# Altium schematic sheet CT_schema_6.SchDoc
size 586 x 434 mm
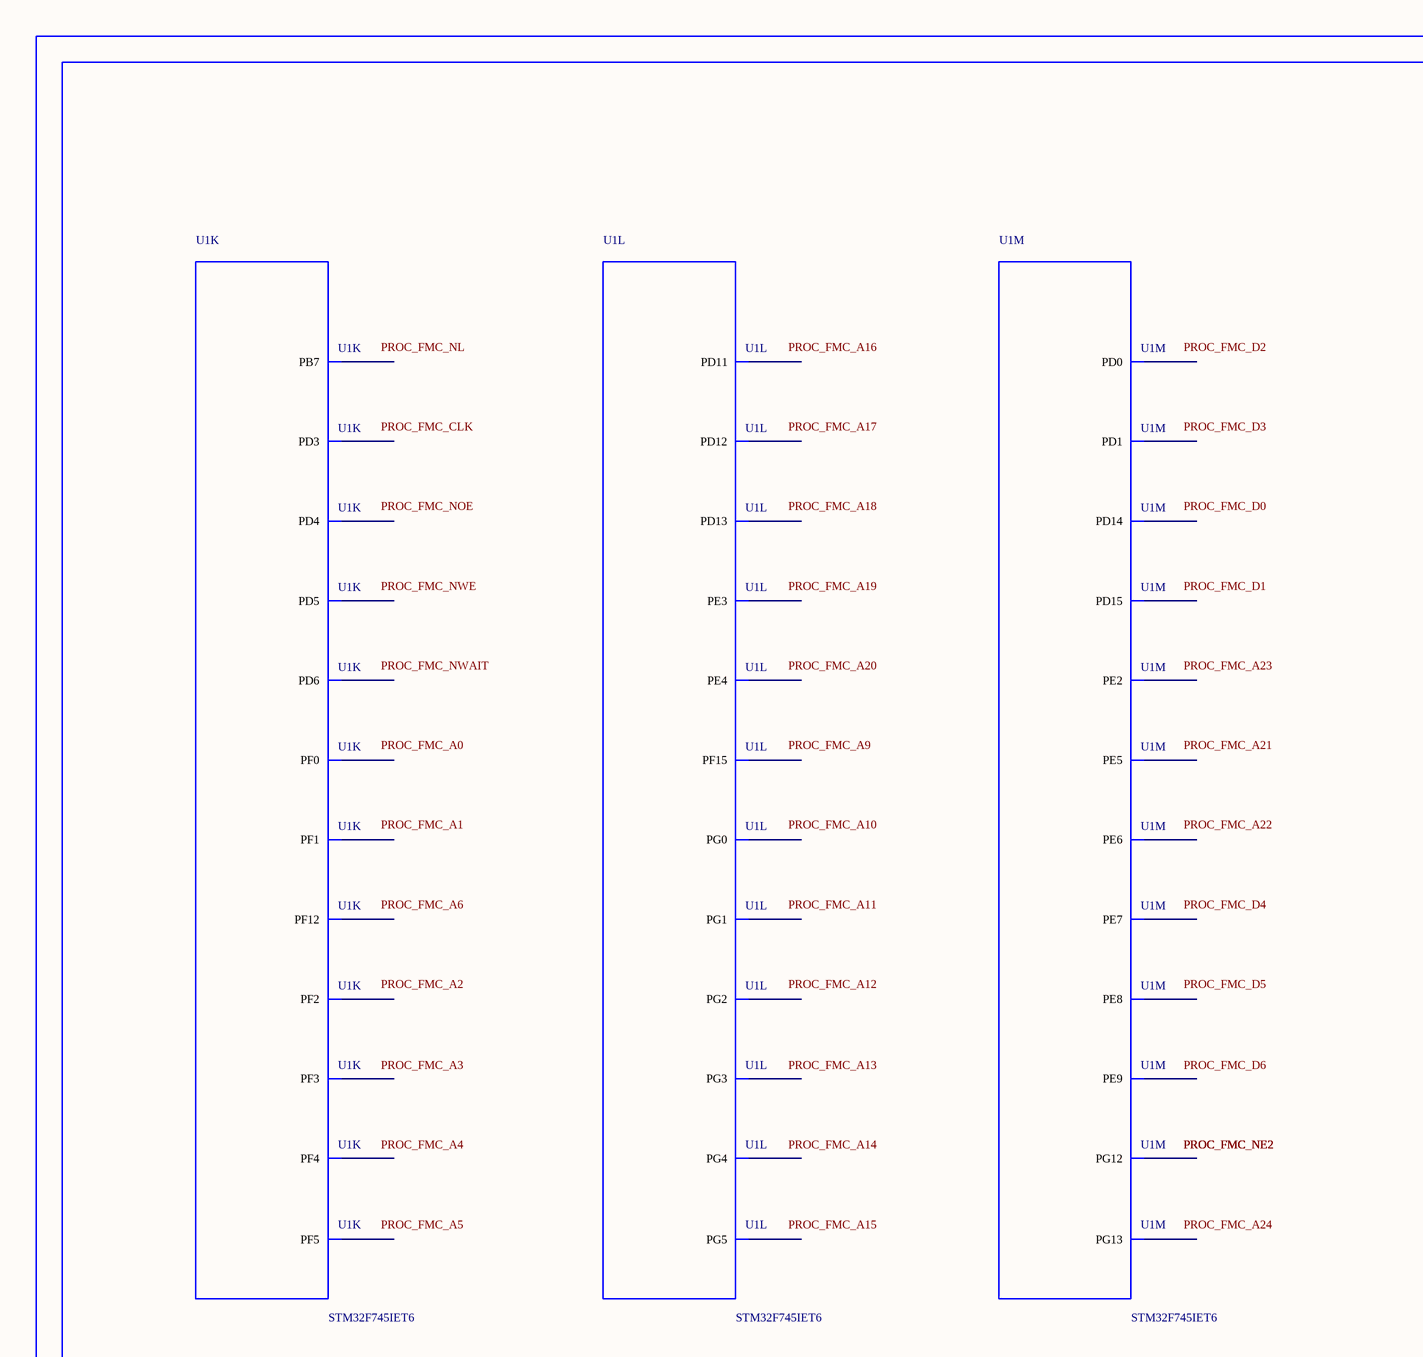
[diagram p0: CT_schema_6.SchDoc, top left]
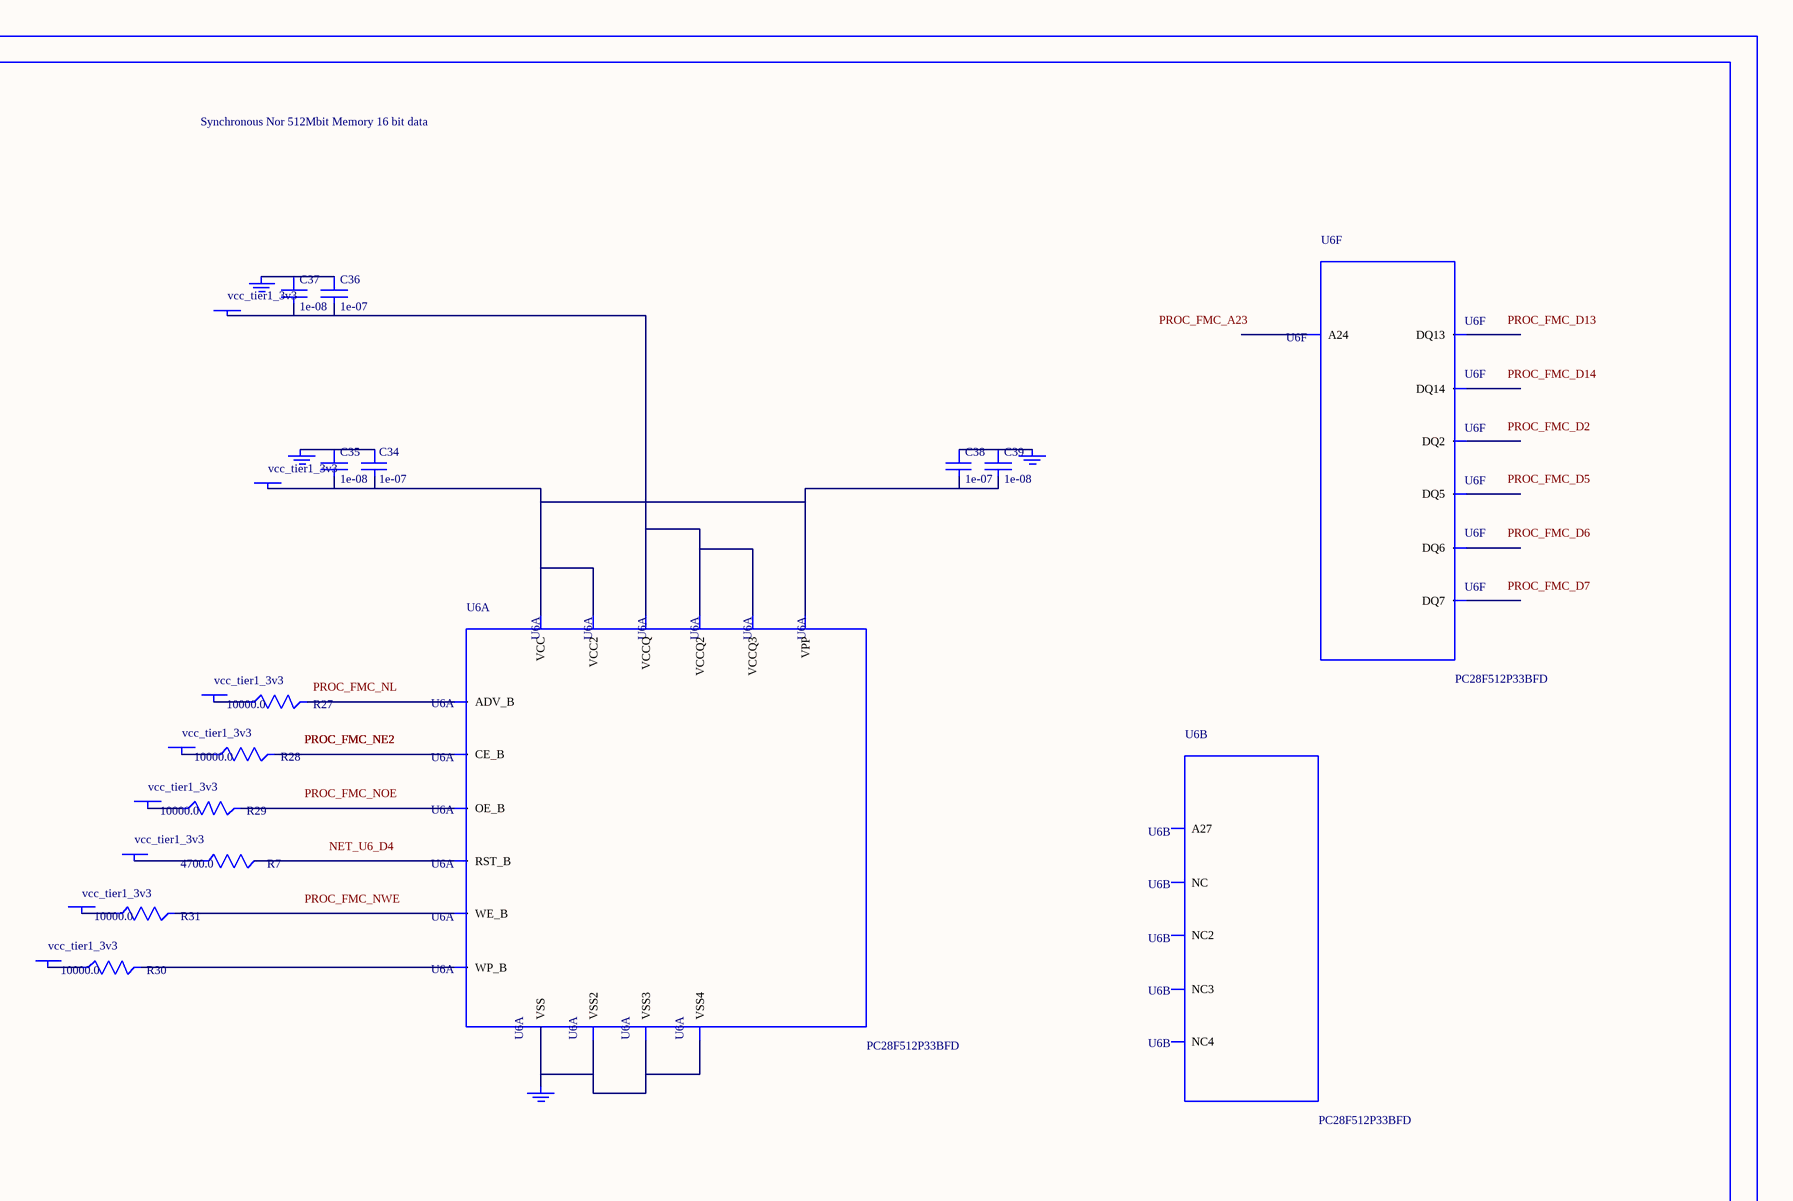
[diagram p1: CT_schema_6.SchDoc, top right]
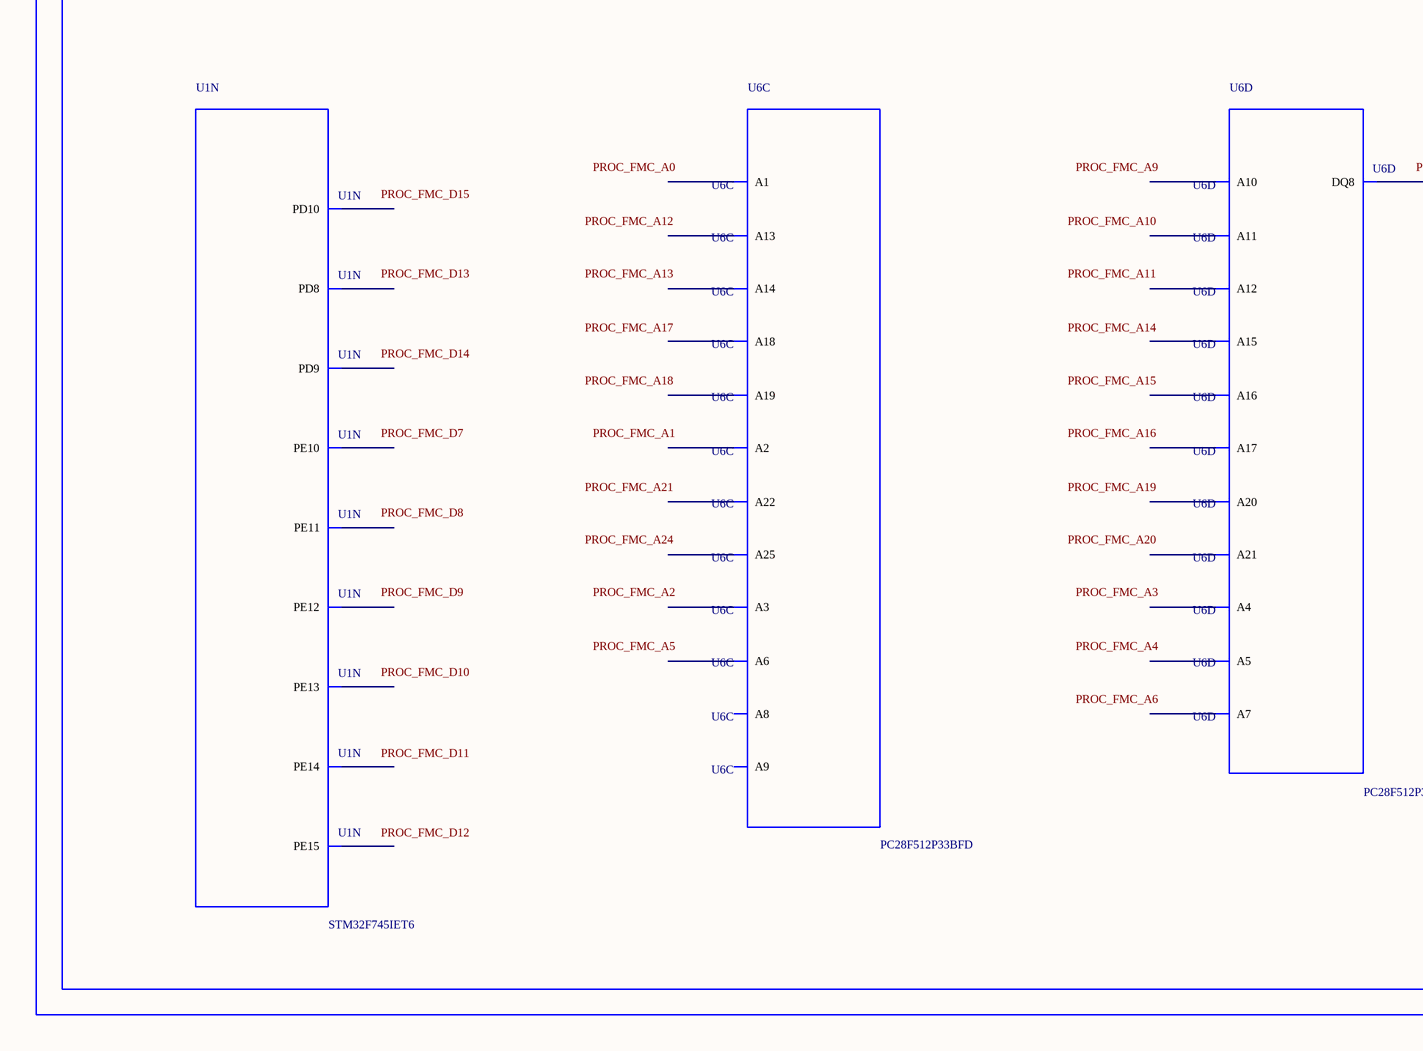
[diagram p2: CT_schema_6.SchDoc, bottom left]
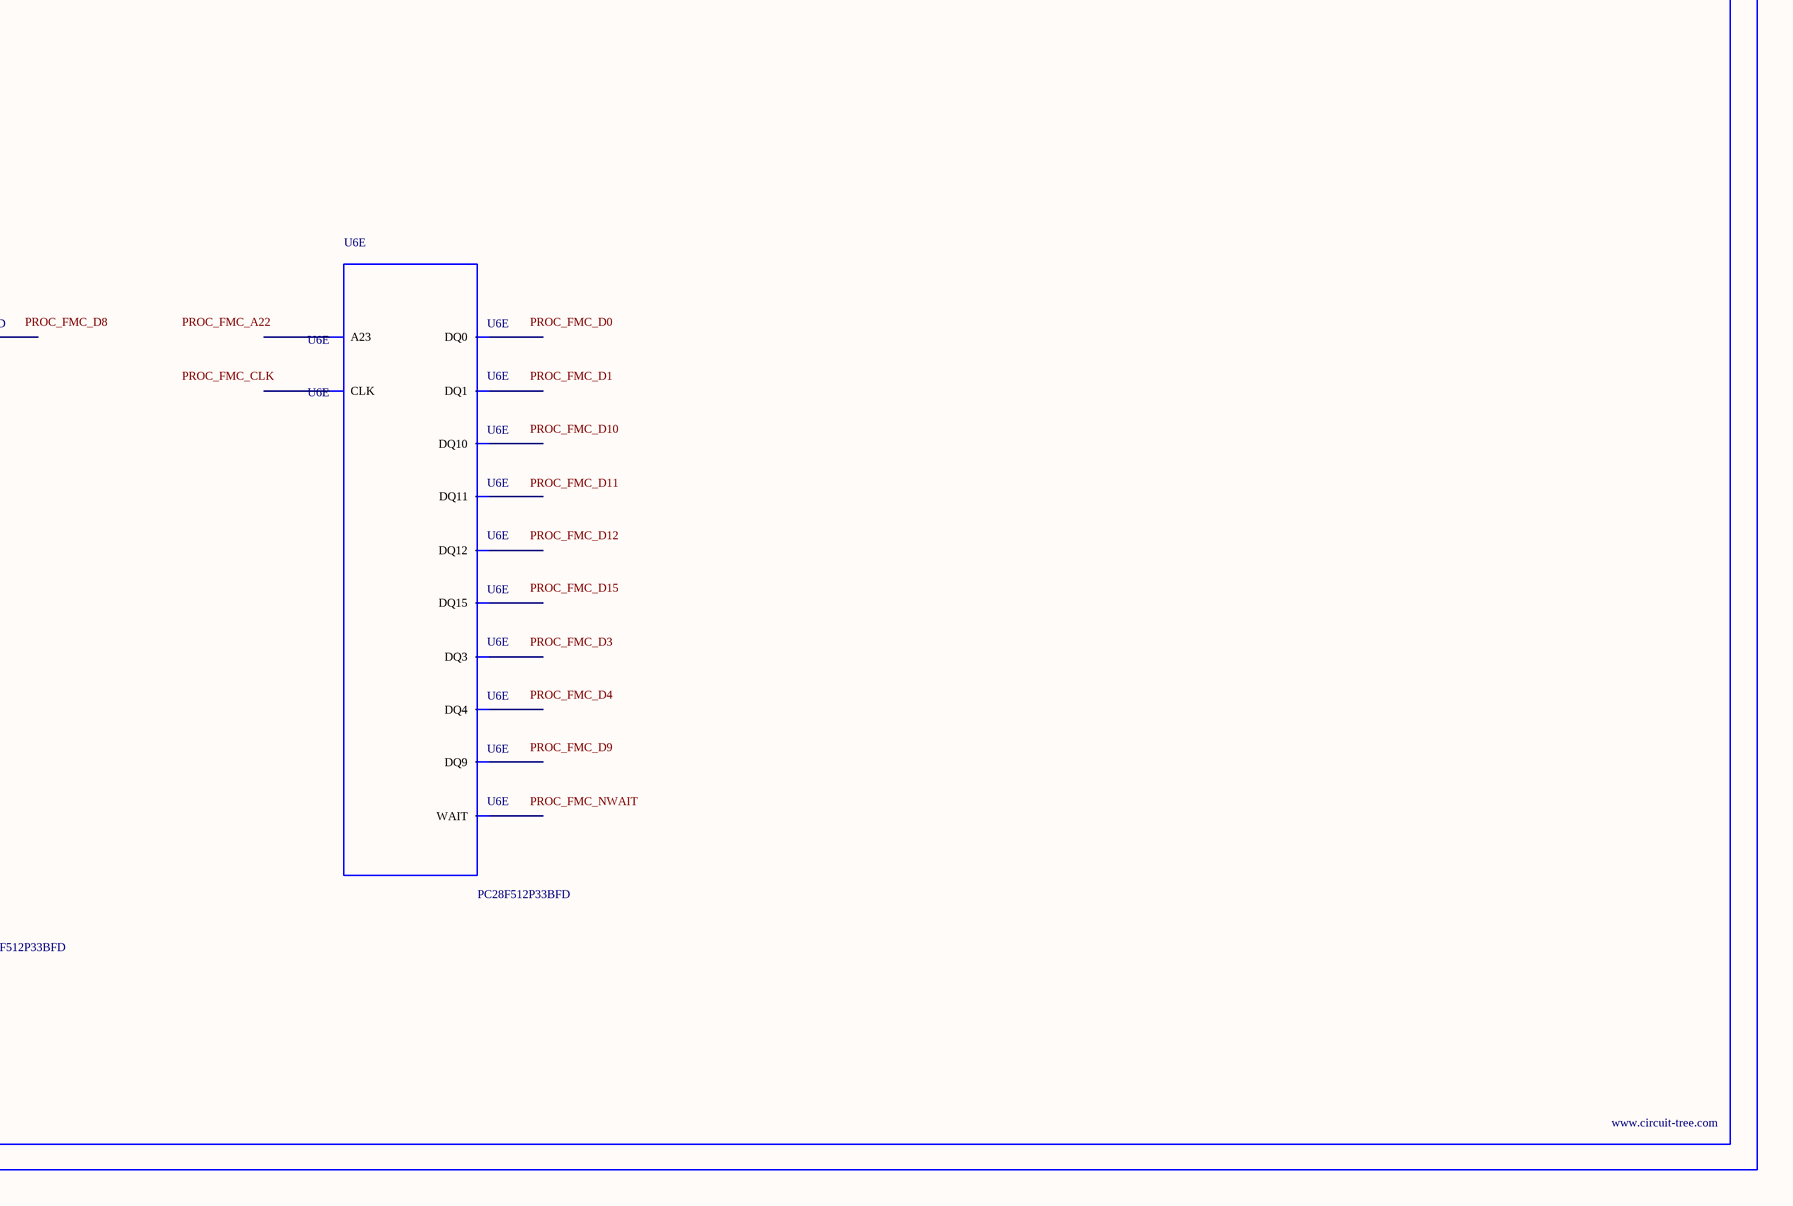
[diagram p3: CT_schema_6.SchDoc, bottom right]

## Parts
BORDER5  (no value)
C34  1e-07  [C0402]
C35  1e-08  [C0402]
C36  1e-07  [C0402]
C37  1e-08  [C0402]
C38  1e-07  [C0402]
C39  1e-08  [C0402]
GND_INSTANCE_5_0  (no value)
GND_INSTANCE_5_1  (no value)
GND_INSTANCE_5_2  (no value)
GND_INSTANCE_5_3  (no value)
POWER_INSTANCE_5_0  vcc_tier1_3v3
POWER_INSTANCE_5_1  vcc_tier1_3v3
POWER_INSTANCE_5_2  vcc_tier1_3v3
POWER_INSTANCE_5_3  vcc_tier1_3v3
POWER_INSTANCE_5_4  vcc_tier1_3v3
POWER_INSTANCE_5_5  vcc_tier1_3v3
POWER_INSTANCE_5_6  vcc_tier1_3v3
POWER_INSTANCE_5_7  vcc_tier1_3v3
R7  4700.0  [R0603]
R27  10000.0  [R0603]
R28  10000.0  [R0603]
R29  10000.0  [R0603]
R30  10000.0  [R0603]
R31  10000.0  [R0603]
U1  STM32F745IET6  [LQFP176]  (parts K,L,M,N of 14)
U6  PC28F512P33BFD  [PC28F512P33BFD]  (parts A,B,C,D,E,F of 6)

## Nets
NetC34_1: C34.1 C35.1 GND_INSTANCE_5_0.0(GND)
NetC34_2: C34.2 C35.2 C38.2 C39.2 POWER_INSTANCE_5_0.0(PWR) U6.A4(VPP) U6.A6(VCC) U6.H3(VCC2)
NetC36_1: C36.1 C37.1 GND_INSTANCE_5_1.0(GND)
NetC36_2: C36.2 C37.2 POWER_INSTANCE_5_1.0(PWR) U6.D5(VCCQ) U6.D6(VCCQ2) U6.G4(VCCQ3)
NetC38_1: C38.1 C39.1 GND_INSTANCE_5_2.0(GND)
NetGND_INSTANCE_5_3_0: GND_INSTANCE_5_3.0(GND) U6.B2(VSS) U6.H2(VSS2) U6.H4(VSS3) U6.H6(VSS4)
NetPOWER_INSTANCE_5_2_0: POWER_INSTANCE_5_2.0(PWR) R27.1
NetPOWER_INSTANCE_5_3_0: POWER_INSTANCE_5_3.0(PWR) R28.1
NetPOWER_INSTANCE_5_4_0: POWER_INSTANCE_5_4.0(PWR) R29.1
NetPOWER_INSTANCE_5_5_0: POWER_INSTANCE_5_5.0(PWR) R30.1
NetPOWER_INSTANCE_5_6_0: POWER_INSTANCE_5_6.0(PWR) R31.1
NetPOWER_INSTANCE_5_7_0: POWER_INSTANCE_5_7.0(PWR) R7.1
NetR7_2: R7.2 U6.D4(RST_B)
NetR27_2: R27.2 U6.F6(ADV_B)
NetR28_2: R28.2 U6.B4(CE_B)
NetR29_2: R29.2 U6.F8(OE_B)
NetR30_2: R30.2 U6.C6(WP_B)
NetR31_2: R31.2 U6.G8(WE_B)

Not connected (* = marked no-connect by the designer): U1 1(PE2) 2(PE3) 3(PE4) 4(PE5) 5(PE6) 16(PF0) 17(PF1) 18(PF2) 19(PF3) 20(PF4) 21(PF5) 60(PF12) 65(PF15) 66(PG0) 67(PG1) 68(PE7) 69(PE8) 70(PE9) 73(PE10) 74(PE11) 75(PE12) 76(PE13) 77(PE14) 78(PE15) 96(PD8) 97(PD9) 98(PD10) 99(PD11) 100(PD12) 101(PD13) 104(PD14) 105(PD15) 106(PG2) 107(PG3) 108(PG4) 109(PG5) 142(PD0) 143(PD1) 145(PD3) 146(PD4) 147(PD5) 150(PD6) 155(PG12) 156(PG13) 165(PB7); U6 A1 A2(A6) A3(A8) A5(A13) A7(A18) A8(A22) B1(A2) B3(A9) B5(A14) B6(A25) B7(A19) B8(NC) C1(A3) C2(A7) C3(A10) C4(A12) C5(A15) C7(A20) C8(A21) D1(A4) D2(A5) D3(A11) D7(A16) D8(A17) E1(DQ8) E2(DQ1) E3(DQ9) E4(DQ3) E5(DQ4) E6(CLK) E7(DQ15) E8(NC2) F1(NC3) F2(DQ0) F3(DQ10) F4(DQ11) F5(DQ12) F7(WAIT) G1(A23) G2(NC4) G3(DQ2) G5(DQ5) G6(DQ6) G7(DQ14) H1(A27) H5(DQ13) H7(DQ7) H8(A24)

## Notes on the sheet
- Labels drawn without touching a wire or pin: NET_U6_D4, PROC_FMC_A0, PROC_FMC_A1, PROC_FMC_A2, PROC_FMC_A3, PROC_FMC_A4, PROC_FMC_A5, PROC_FMC_A6, PROC_FMC_A9, PROC_FMC_A10, PROC_FMC_A11, PROC_FMC_A12, PROC_FMC_A13, PROC_FMC_A14, PROC_FMC_A15, PROC_FMC_A16, PROC_FMC_A17, PROC_FMC_A18, PROC_FMC_A19, PROC_FMC_A20, PROC_FMC_A21, PROC_FMC_A22, PROC_FMC_A23, PROC_FMC_A24, PROC_FMC_CLK, PROC_FMC_D0, PROC_FMC_D1, PROC_FMC_D2, PROC_FMC_D3, PROC_FMC_D4, PROC_FMC_D5, PROC_FMC_D6, PROC_FMC_D7, PROC_FMC_D8, PROC_FMC_D9, PROC_FMC_D10, PROC_FMC_D11, PROC_FMC_D12, PROC_FMC_D13, PROC_FMC_D14, PROC_FMC_D15, PROC_FMC_NL, PROC_FMC_NOE, PROC_FMC_NWAIT, PROC_FMC_NWE

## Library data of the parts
BORDER5 = BORDER_PAGE5
C34 C36 C38 = C0402C104K3RACTU
C35 C37 C39 = C0402C103K3RAC
GND_INSTANCE_5_0-GND_INSTANCE_5_3 = GND
POWER_INSTANCE_5_0-POWER_INSTANCE_5_7 = PWR
R7 = RC0603JR-074K7L
R27-R31 = RC0603JR-0710KL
